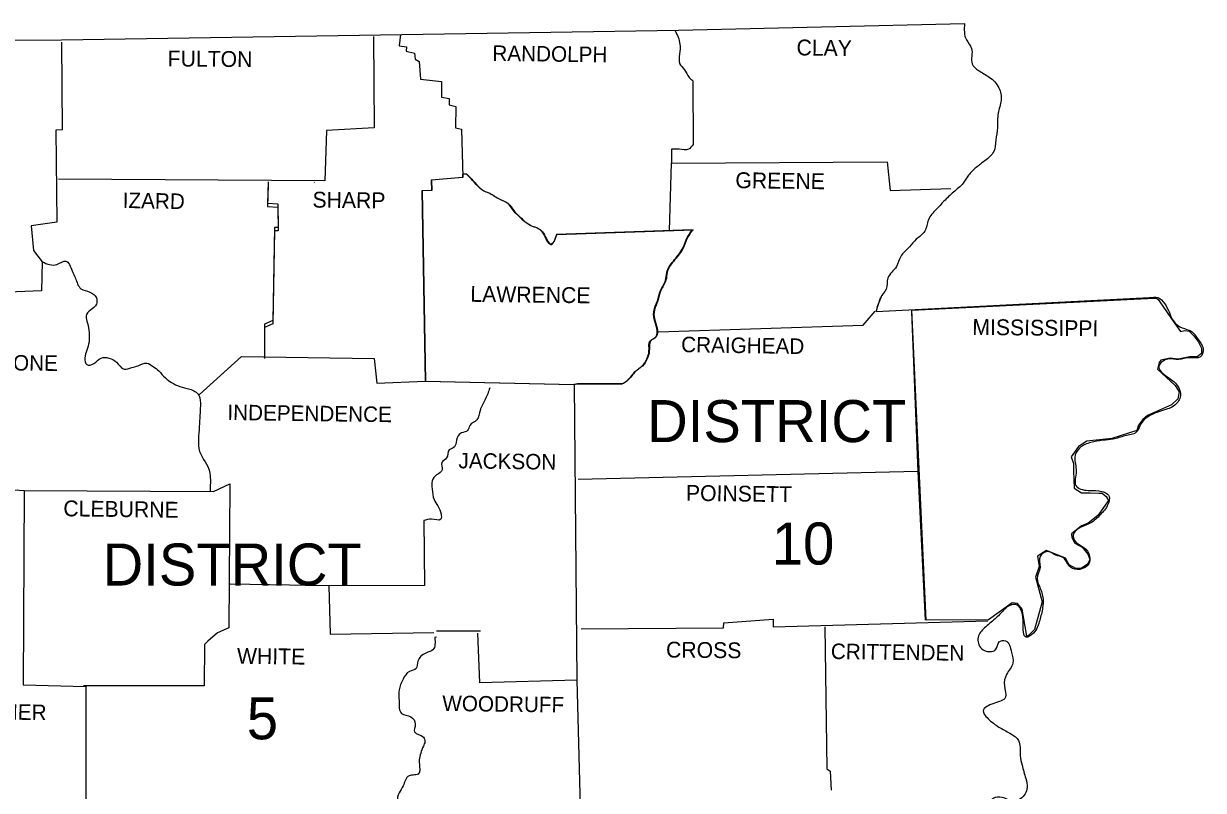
# Model space of a CAD drawing. Extents: x -42408 to 34530, y -43140 to 20491.
# Drawn here: x 9102 to 10705, y 9002 to 10043 of the extents above; entities that cross this region are included whole.
import ezdxf

# ---------------------------------------------------------------- set-up
doc = ezdxf.new("R2010")
doc.units = 0
for name, color, linetype in [('1', 7, 'Continuous'), ('2', 7, 'Continuous'), ('3', 7, 'Continuous'), ('S_MISC_BOUNDARY', 7, 'Continuous')]:
    doc.layers.add(name, color=color, linetype=linetype)

msp = doc.modelspace()

# ---------------------------------------------------------------- linework, layer by layer
at = {"layer": '1'}
for p, q in [((9982.4, 9872.3), (9982.4, 9853.7)), ((9704, 9838.7), (9698.4, 9838.5)), ((10010.4, 9763.1), (9826.2, 9756.6)), ((9978.8, 9761.6), (9979.7, 9762.5)), ((9818.7, 9743), (9823.5, 9747.8)), ((10260.2, 9652), (10266.3, 9670.5)), ((10261.7, 9658), (10267.8, 9672.5)), ((10308.7, 9653.8), (10638.1, 9670)), ((10638.1, 9670), (10640.9, 9670.1)), ((10640.9, 9670.1), (10643.2, 9668.5)), ((10643.2, 9668.5), (10649.6, 9659.4)), ((10328.2, 9232.9), (10308.7, 9653.8)), ((10649.6, 9659.4), (10661.6, 9642.1)), ((10661.6, 9642.1), (10673.6, 9624.8)), ((10673.6, 9624.8), (10679.6, 9626.4)), ((10679.6, 9626.4), (10685.7, 9625.4)), ((10685.7, 9625.4), (10691.3, 9619.7)), ((10691.3, 9619.7), (10697.5, 9611.4)), ((10697.5, 9611.4), (10702.3, 9602.1)), ((10702.3, 9602.1), (10702.4, 9595.1)), ((10644.8, 9583), (10642.5, 9573.8)), ((10646.9, 9585.8), (10644.8, 9583)), ((10659.8, 9588.6), (10646.9, 9585.8)), ((10670.4, 9587.4), (10659.8, 9588.6)), ((10686.5, 9590.6), (10670.4, 9587.4)), ((10696.2, 9590.7), (10686.5, 9590.6)), ((10702.4, 9595.1), (10696.2, 9590.7)), ((10642.5, 9573.8), (10666.6, 9551.4)), ((10666.6, 9551.4), (10672.1, 9543.2)), ((10672.1, 9543.2), (10669.9, 9533.5)), ((10661.7, 9525.3), (10629.1, 9510.8)), ((10669.9, 9533.5), (10661.7, 9525.3)), ((10622.6, 9505.4), (10616.8, 9497.7)), ((10629.1, 9510.8), (10622.6, 9505.4)), ((10614.2, 9490.4), (10580.3, 9479.7)), ((10616.8, 9497.7), (10614.2, 9490.4)), ((10546.6, 9476.1), (10535.3, 9468.8)), ((10580.3, 9479.7), (10546.6, 9476.1)), ((10535.3, 9468.8), (10525.3, 9454.7)), ((10525.3, 9454.7), (10528.4, 9445.6)), ((10528.4, 9445.6), (10528.4, 9435.9)), ((10528.4, 9435.9), (10529.3, 9412.1)), ((10529.3, 9412.1), (10539.4, 9406)), ((10539.4, 9406), (10551.1, 9405.7)), ((10551.1, 9405.7), (10562.8, 9405.3)), ((10575.9, 9395.6), (10561.5, 9375.2)), ((10562.8, 9405.3), (10567.1, 9405.2)), ((10567.1, 9405.2), (10572.6, 9401)), ((10572.6, 9401), (10575.9, 9395.6)), ((10561.5, 9375.2), (10548.1, 9364.9)), ((10539.2, 9361.2), (10525.8, 9350.3)), ((10548.1, 9364.9), (10539.2, 9361.2)), ((10525.8, 9350.3), (10526.2, 9345.2)), ((10526.2, 9345.2), (10530.4, 9337.4)), ((10491.5, 9327.7), (10479.6, 9320.1)), ((10502.9, 9323), (10491.5, 9327.7)), ((10530.4, 9337.4), (10540.2, 9331.9)), ((10540.2, 9331.9), (10547.8, 9322.7)), ((10479.6, 9320.1), (10480.2, 9314.2)), ((10480.2, 9314.2), (10481.9, 9305.7)), ((10517.7, 9317), (10502.9, 9323)), ((10522.6, 9308), (10517.7, 9317)), ((10550.4, 9315.5), (10547.5, 9309.1)), ((10547.8, 9322.7), (10550.4, 9315.5)), ((10481.9, 9305.7), (10476.9, 9291.2)), ((10531.5, 9303), (10522.6, 9308)), ((10538.6, 9303.3), (10531.5, 9303)), ((10547.5, 9309.1), (10538.6, 9303.3)), ((10476.9, 9291.2), (10485.8, 9257.9)), ((10445, 9256.3), (10412.9, 9233.5)), ((10452.3, 9255.8), (10445, 9256.3)), ((10458.8, 9247.7), (10452.3, 9255.8)), ((10465.1, 9211.4), (10458.8, 9247.7)), ((10485.8, 9257.9), (10475.2, 9220.5)), ((10412.9, 9233.5), (10328.2, 9232.9)), ((9663.4, 9218.4), (9723, 9218.4)), ((10475.2, 9220.5), (10467.9, 9212.4)), ((10467.9, 9212.4), (10465.1, 9211.4))]:
    msp.add_line(p, q, dxfattribs=at)
for points in [[(7633.7, 10020), (8443.3, 10019.5), (9153.8, 10021), (9991.9, 10034), (10380.4, 10043)], [(9153.8, 10018), (9154.8, 9898.8), (9146.3, 9898.3), (9147.8, 9773.6), (9112.7, 9768.6), (9115.7, 9735.1), (9127.7, 9719.6), (9126.7, 9680), (9058.6, 9677.5), (9056.1, 9616.4), (8994.1, 9614.4), (8991, 9540.3), (8994.6, 9534.3), (8996.1, 9416.2), (9103.2, 9409.1), (9101.7, 9145.3), (9186.8, 9142.8), (9186.8, 8874.4), (9119.7, 8869.4), (9114.7, 8810.3), (9002.1, 8809.8)], [(9577.8, 10025.5), (9578.8, 9901.3), (9513.7, 9897.8), (9511.7, 9829.7), (9149.8, 9831.7)], [(9614.3, 10028.1), (9612.4, 10012.9), (9622.4, 10011.4), (9621.9, 10005.4), (9633.4, 10002.9), (9634.4, 9994.9), (9639.9, 9991.4), (9641.4, 9967.4), (9670, 9964.4), (9670, 9942.9), (9680.5, 9941.4), (9680.5, 9932.8), (9689.5, 9930.3), (9689, 9901.3), (9697, 9899.8), (9699, 9834.2), (9656.4, 9830.2), (9656.9, 9816.2), (9643.9, 9815.7), (9648.4, 9557.3), (9850.2, 9552.8), (9853.7, 9151.3), (9722, 9147.8), (9719.5, 9215.4)], [(10011.4, 9965.4), (10011.9, 9878.8)], [(9979.7, 9762), (9982.4, 9853.7), (9982.4, 9853.7), (10275.3, 9855.2), (10279.3, 9816.2), (10361.9, 9819.2)], [(9434.6, 9828.2), (9433.6, 9799.2), (9447.7, 9798.2), (9448.2, 9766.1), (9443.2, 9766.1), (9441.1, 9640), (9429.6, 9634.9), (9429.6, 9592.9)], [(9434.6, 9823.7), (9433.6, 9794.7), (9447.7, 9793.7), (9448.2, 9761.6), (9443.2, 9761.6), (9441.1, 9635.4), (9429.6, 9630.4), (9429.6, 9588.4)], [(9497.2, 9827.2), (9497.7, 9827.7)], [(9698.4, 9838.5), (9698.5, 9834.2), (9655.9, 9830.2), (9656.4, 9816.2), (9643.4, 9815.7), (9647.9, 9557.3), (9849.7, 9552.8)], [(9826.7, 9756.6), (10012.4, 9763.1)], [(10010.4, 9762.6), (10010.4, 9763.1)], [(10260.2, 9652), (10640.2, 9671.5)], [(9964.8, 9624.4), (10242.7, 9633.4), (10259.2, 9652.5)], [(10308.3, 9651.5), (10316.8, 9434.7), (10326.8, 9232.9)], [(9341.5, 9539.3), (9398.6, 9590.9), (9578.8, 9588.4), (9582.3, 9554.8), (9647.9, 9557.3)], [(9849.7, 9552.8), (9854.2, 9553.8), (9915.3, 9553.8)], [(9915.8, 9553.8), (9854.7, 9553.8), (9850.2, 9552.8)], [(10316.8, 9434.7), (9855.7, 9424.2)], [(9103.2, 9409.1), (9360.5, 9407.6), (9382.6, 9418.2), (9381.1, 9222.4), (9366, 9215.9), (9352.5, 9204.4), (9348, 9199.9), (9347.5, 9143.8), (9183.8, 9143.8)], [(9645.9, 9368.1), (9646.9, 9280), (9516.8, 9279.5), (9383.1, 9282)], [(9516.8, 9279.5), (9518.8, 9213.9), (9659.4, 9216.4)], [(9859.7, 9221.4), (10053, 9222.4), (10053.5, 9229.4), (10120.6, 9234.4), (10120.6, 9223.9), (10411.9, 9231.9)], [(10190.6, 9223.9), (10193.2, 9031.1), (10197.7, 9028.1), (10199.2, 9002.1)], [(9663.4, 9209.9), (9660.9, 9209.4)], [(9853.7, 9151.3), (9861.2, 8876.9), (9742.1, 8876.4), (9741.6, 8865.4), (9707, 8863.4), (9704, 8806.3), (9661.9, 8806.3)]]:
    msp.add_lwpolyline(points, dxfattribs=at)
for points in [[(9987.1, 10033.9), (9993.9, 10015), (9993.4, 10001.4), (9993.4, 9988.9), (9999.9, 9980.4), (10006.4, 9969.9), (10011.4, 9965.4)], [(10380.4, 10043), (10382.9, 10021), (10389.9, 10009.4), (10390.9, 9988.4), (10399.4, 9979.4), (10413.9, 9970.4), (10427, 9955.9), (10430, 9938.8), (10426, 9921.3), (10425, 9901.8), (10423, 9884.8), (10420, 9869.3), (10407.9, 9856.7), (10396.4, 9847.7), (10385.9, 9837.2), (10378.4, 9826.2), (10365.4, 9814.2), (10352.4, 9801.7), (10341.9, 9790.7), (10331.3, 9776.6), (10326.3, 9761.1), (10314.8, 9750.1), (10305.8, 9740.1), (10293.8, 9726.6), (10287.8, 9713), (10276.3, 9697.5), (10273.8, 9682.5), (10266.3, 9670.5), (10265.7, 9668.5)], [(10011.9, 9878.8), (10005.4, 9872.3), (9992.9, 9872.3), (9982.4, 9872.3)], [(9826.2, 9756.6), (9818.2, 9743.1), (9810.6, 9753.6), (9805.1, 9762.1), (9788.6, 9770.1), (9778.1, 9778.6), (9767.6, 9789.1), (9760.1, 9798.7), (9748.6, 9804.7), (9735.5, 9812.2), (9724.5, 9817.7), (9715, 9827.2), (9704, 9838.7)], [(9704.5, 9838.7), (9715.5, 9827.2), (9725, 9817.7), (9736, 9812.2), (9749.1, 9804.7), (9760.6, 9798.7), (9768.1, 9789.1), (9778.6, 9778.6), (9789.1, 9770.1), (9805.6, 9762.1), (9811.1, 9753.6), (9818.7, 9743.1), (9826.7, 9756.6)], [(9915.3, 9553.8), (9922.8, 9558.8), (9932.8, 9570.4), (9942.3, 9577.9), (9948.8, 9587.9), (9951.8, 9597.9), (9953.8, 9612.4), (9961.3, 9617.9), (9962.3, 9629.4), (9958.8, 9642), (9958.8, 9654.5), (9963.3, 9666.5), (9967.4, 9680.5), (9974.4, 9694.5), (9975.9, 9705), (9984.9, 9720.6), (9996.9, 9736.6), (10002.9, 9750.6), (10010.4, 9762.6)], [(10010.9, 9762.6), (10003.4, 9750.6), (9997.4, 9736.6), (9985.4, 9720.6), (9976.4, 9705), (9974.9, 9694.5), (9967.9, 9680.5), (9963.8, 9666.5), (9959.3, 9654.5), (9959.3, 9642), (9962.8, 9629.4), (9961.8, 9617.9), (9954.3, 9612.4), (9952.3, 9597.9), (9949.3, 9587.9), (9942.8, 9577.9), (9933.3, 9570.4), (9923.3, 9558.8), (9915.8, 9553.8)], [(9127.7, 9719.6), (9147.8, 9716.1), (9159.8, 9720.6), (9168.3, 9707.5), (9172.8, 9697.5), (9180.3, 9683), (9192.3, 9678.5), (9201.3, 9670.5), (9201.3, 9662), (9193.3, 9654), (9187.3, 9646), (9189.3, 9636.4), (9191.3, 9623.4), (9191.3, 9610.9), (9188.3, 9599.4), (9185.8, 9588.9), (9188.3, 9579.9), (9197.8, 9581.4), (9207.8, 9588.9), (9218.4, 9588.9), (9228.4, 9583.4), (9238.9, 9573.9), (9249.4, 9575.9), (9257.9, 9578.4), (9269.9, 9581.9), (9278.4, 9577.4), (9285.9, 9571.4), (9295, 9561.8), (9303.5, 9555.8), (9314.5, 9550.3), (9328, 9546.8), (9340.5, 9538.3), (9342.5, 9523.8), (9342, 9511.3), (9341, 9495.8), (9340, 9478.7), (9341.5, 9462.2), (9347, 9451.2), (9354, 9438.2), (9356, 9426.2), (9355.5, 9407.1)], [(10634.7, 9671), (10640.2, 9671.5), (10657.3, 9653.5), (10664.8, 9638.4), (10675.8, 9629.9), (10688.3, 9625.4), (10697.8, 9613.9), (10704.3, 9601.4), (10700.8, 9590.4), (10686.8, 9589.4), (10671.3, 9586.9), (10656.3, 9587.4), (10644.3, 9577.4), (10655.3, 9563.8), (10669.8, 9551.3), (10673.8, 9537.8), (10665.8, 9524.8), (10649.8, 9517.8), (10634.2, 9511.8), (10620.2, 9499.8), (10613.7, 9488.2), (10598.2, 9483.2), (10582.2, 9478.7), (10568.2, 9477.2), (10552.1, 9474.2), (10536.6, 9466.7), (10530.1, 9453.7), (10532.1, 9435.2), (10531.6, 9415.7), (10548.1, 9409.1), (10562.6, 9408.6), (10576.7, 9401.1), (10575.2, 9390.1), (10564.6, 9376.1), (10552.1, 9365.1), (10539.6, 9359.6), (10528.1, 9349.1), (10532.1, 9338.5), (10542.6, 9331.5), (10550.1, 9320), (10549.1, 9309.5), (10537.1, 9302), (10524.1, 9305), (10514.6, 9317.5), (10503.6, 9321.5), (10494.1, 9326), (10483, 9319.5), (10483, 9305), (10479, 9289.5), (10482.5, 9278), (10487, 9261.9), (10486.5, 9249.9), (10482.5, 9232.9), (10474, 9215.4), (10464, 9209.9), (10460, 9228.9), (10458, 9244.4), (10452, 9253.4), (10444, 9253.9), (10433.5, 9246.4), (10422, 9234.9), (10407.4, 9222.4), (10398.9, 9209.9), (10403.4, 9194.4), (10414.4, 9190.4), (10423, 9193.4), (10427.5, 9203.4), (10436, 9204.9), (10444, 9189.3)], [(9735.5, 9548.3), (9729.5, 9532.8), (9722.5, 9517.8), (9718, 9504.8), (9708.5, 9497.3), (9705.5, 9490.3), (9697, 9487.2), (9690.5, 9477.2), (9687.5, 9468.2), (9680.5, 9464.2), (9677, 9453.2), (9670.5, 9447.2), (9671, 9437.2), (9663.4, 9430.2), (9657.4, 9422.2), (9657.4, 9411.1), (9659.9, 9396.6), (9664.9, 9388.1), (9669.5, 9377.1), (9669, 9370.1), (9656.4, 9370.1), (9645.9, 9368.1)], [(9660.9, 9209.4), (9658.4, 9192.9), (9648.9, 9188.3), (9637.9, 9177.3), (9635.4, 9167.3), (9626.4, 9163.3), (9617.9, 9152.8), (9612.4, 9138.3), (9612.4, 9123.3), (9615.9, 9106.2), (9628.4, 9101.7), (9634.4, 9091.7), (9633.4, 9081.2), (9645.4, 9074.2), (9647.4, 9068.2), (9645.4, 9061.7), (9639.9, 9043.2), (9640.4, 9030.6), (9639.4, 9025.1), (9625.9, 9021.6), (9617.9, 9008.1), (9612.4, 8998.6), (9610.4, 8986.1), (9611.9, 8977.1), (9607.9, 8970.1), (9606.4, 8959.5), (9601.4, 8950.5), (9596.9, 8942), (9601.9, 8932), (9600.4, 8925), (9597.4, 8914), (9599.9, 8910.5)], [(10444, 9189.3), (10446, 9174.8), (10437.5, 9159.3), (10434.5, 9143.8), (10436, 9128.3), (10420, 9119.8), (10405.9, 9109.7), (10413.9, 9097.7), (10429, 9086.7), (10444, 9078.2), (10453.5, 9069.7), (10456, 9049.2), (10458.5, 9036.1), (10463.5, 9018.1), (10465.5, 9005.6), (10456.5, 8990.6), (10446, 8987.6), (10435, 8991.1), (10422, 8992.1), (10411.4, 8982.1), (10403.9, 8968.1), (10396.4, 8954), (10390.9, 8942), (10385.4, 8929), (10374.4, 8914), (10360.9, 8911.5), (10344.9, 8907.5), (10335.3, 8896.5), (10336.8, 8877.9), (10345.9, 8865.4), (10352.9, 8849.9), (10357.9, 8836.4), (10355.4, 8819.4), (10348.4, 8806.8), (10339.3, 8799.3), (10335.3, 8783.3), (10328.8, 8771.3), (10322.8, 8767.3), (10310.8, 8768.3), (10297.8, 8770.8), (10286.8, 8769.8), (10276.3, 8764.3), (10265.7, 8767.8), (10254.7, 8779.8), (10245.7, 8788.8), (10235.7, 8792.3), (10225.2, 8786.8), (10223.2, 8770.3), (10228.2, 8753.3), (10232.7, 8730.2), (10228.2, 8716.2), (10226.7, 8693.2)]]:
    msp.add_spline(points, degree=3, dxfattribs=at)
at = {"layer": 'S_MISC_BOUNDARY'}
msp.add_line((9704.5, 9838.7), (9698.9, 9838.5), dxfattribs=at)

# ---------------------------------------------------------------- texts
at = {"layer": '2'}
for s, height, rotation, p in [('CLAY', 21.52, 359.2258, (10152.1, 9999.9)), ('FULTON', 21.52, 359.4996, (9298, 9984.9)), ('RANDOLPH', 21.03, 359.2583, (9739, 9992.4)), ('GREENE', 21.53, 359.2361, (10069, 9819.7)), ('IZARD', 21.02, 358.9258, (9236.9, 9792.7)), ('SHARP', 21.52, 359.3905, (9494.7, 9793.2)), ('LAWRENCE', 21.53, 359.2678, (9709.1, 9665.3)), ('MISSISSIPPI', 21.524, 359.3097, (10390.9, 9620.4)), ('CRAIGHEAD', 21.03, 359.1159, (9995.4, 9596.9)), ('STONE', 21.02, 359.4001, (9052.1, 9572.4)), ('INDEPENDENCE', 21.022, 359.2187, (9379.1, 9504.8)), ('JACKSON', 21.02, 359.1352, (9693, 9439.2)), ('POINSETT', 21.52, 359.1987, (10001.9, 9395.1)), ('CLEBURNE', 21.52, 359.2535, (9156.3, 9374.1)), ('CROSS', 21.52, 359.3839, (9974.9, 9182.3)), ('CRITTENDEN', 21.03, 359.213, (10198.7, 9180.3)), ('WHITE', 21.53, 359.3139, (9392.1, 9173.8)), ('FAULKNER', 21.03, 359.2486, (8983.5, 9099.2)), ('WOODRUFF', 21.02, 359.2748, (9671, 9109.7))]:
    msp.add_text(s, height=height, rotation=rotation, dxfattribs=at).set_placement(p)
at = {"layer": '3'}
for s, height, p in [('DISTRICT', 57.08, (9949.3, 9474.7)), ('10', 57.08, (10118.6, 9308.5)), ('DISTRICT', 57.08, (9209.8, 9280)), ('5', 57.1, (9405.6, 9071.2))]:
    msp.add_text(s, height=height, dxfattribs=at).set_placement(p)

doc.saveas('drawing.dxf')
